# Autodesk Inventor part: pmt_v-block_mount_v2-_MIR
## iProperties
Shininess: 64.0
Length Units: 11272
Angle Units: 11279
Time Units: 11290
Mass Units: 11286
Length Display Precision: 3
Angle Display Precision: 2
Compacted: True
Part Number: pmt_v-block_mount_v2-_MIR
Document SubType Name: Modeling
Created: 2004-08
Designer: John Blackburn
Material: Default
Manufacturer: Standard
Standards Organization: Custom
Density: 0.0
Volumn: 0.0
Area: 0.0
PropertySet Name: Model Information
Control State: 0
Master: False
Checked Out: False
Author: John Blackburn
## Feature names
1. Derived Body1 [Tagging]
